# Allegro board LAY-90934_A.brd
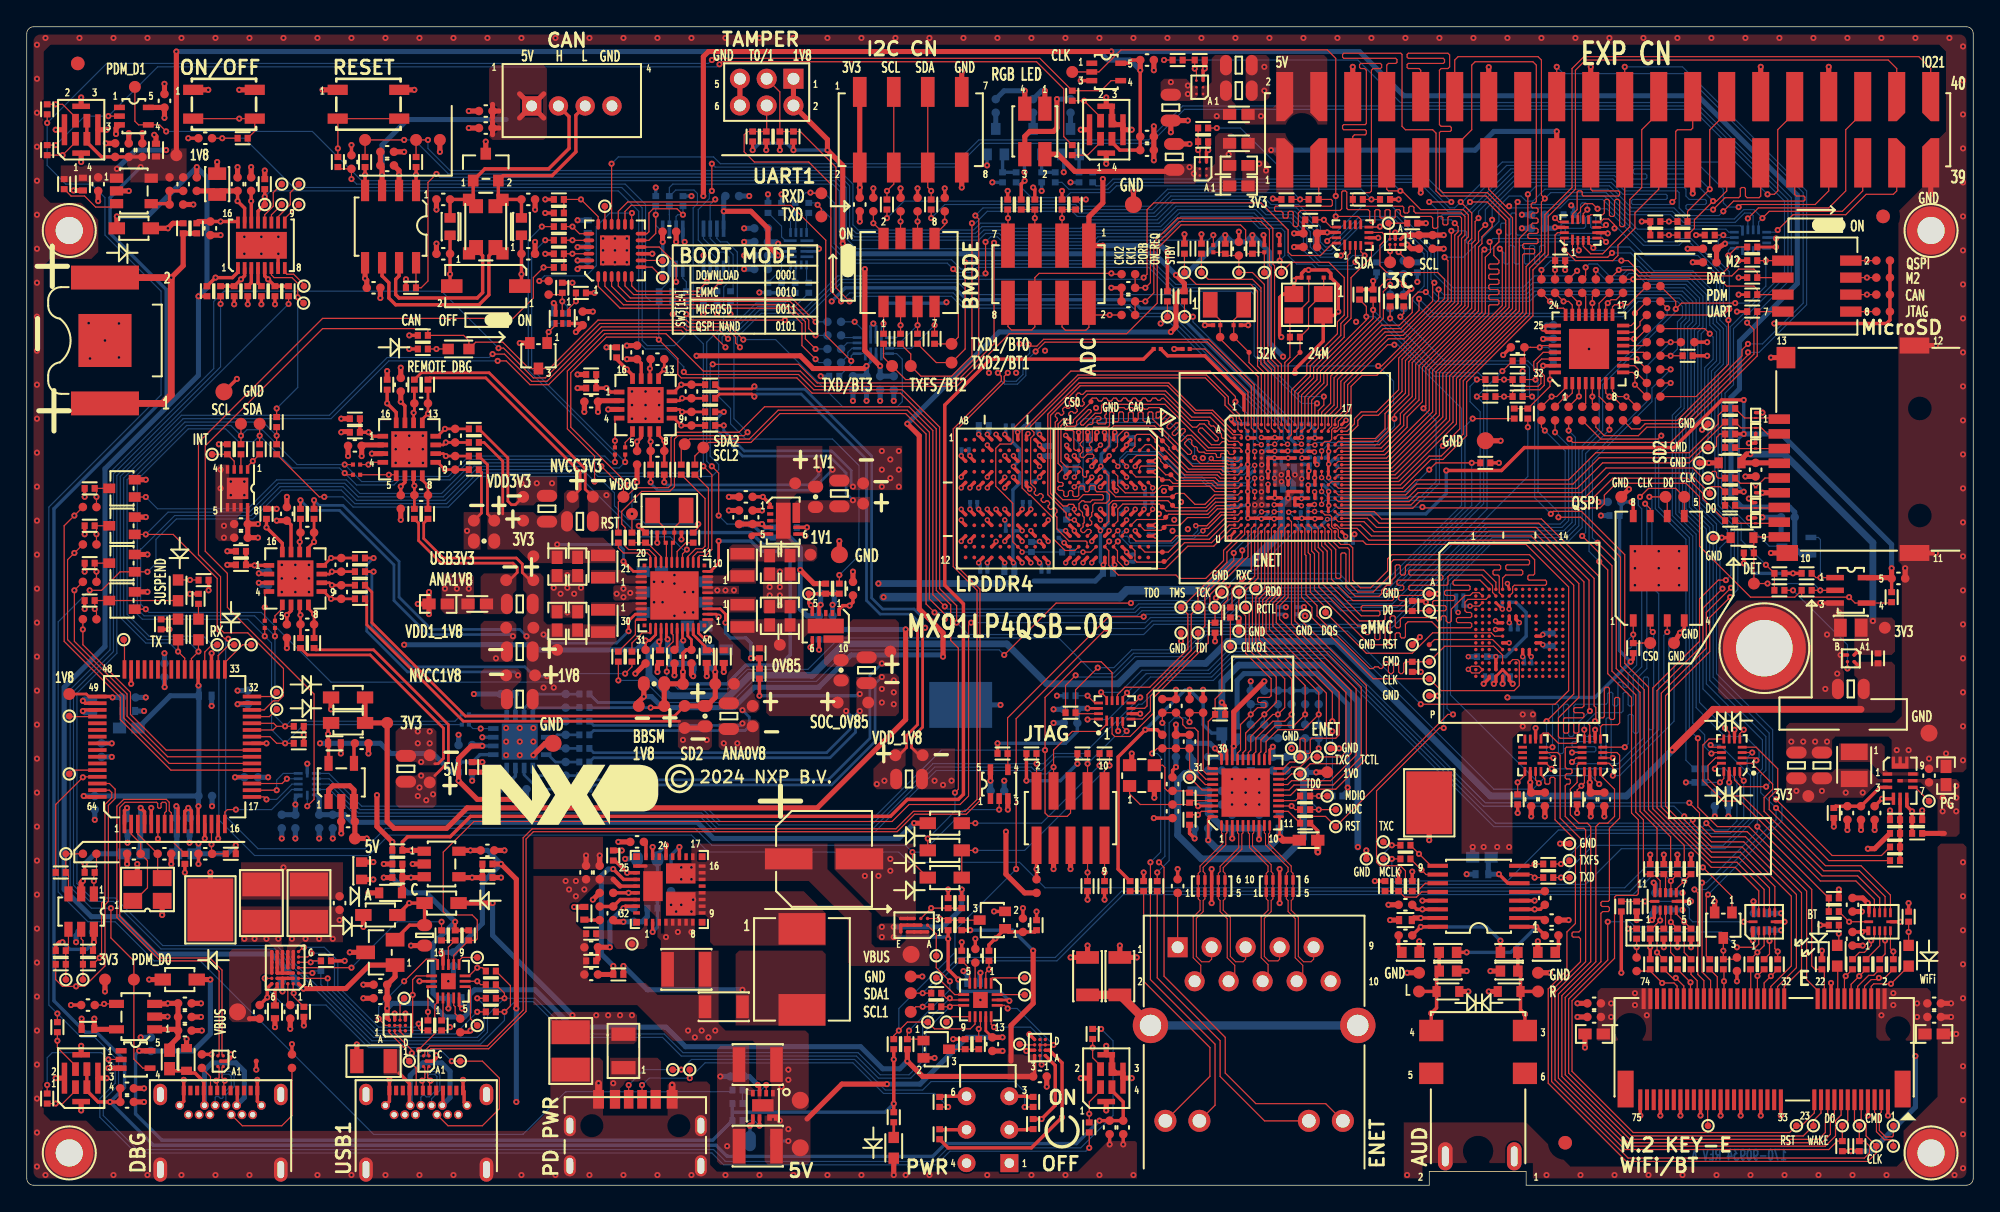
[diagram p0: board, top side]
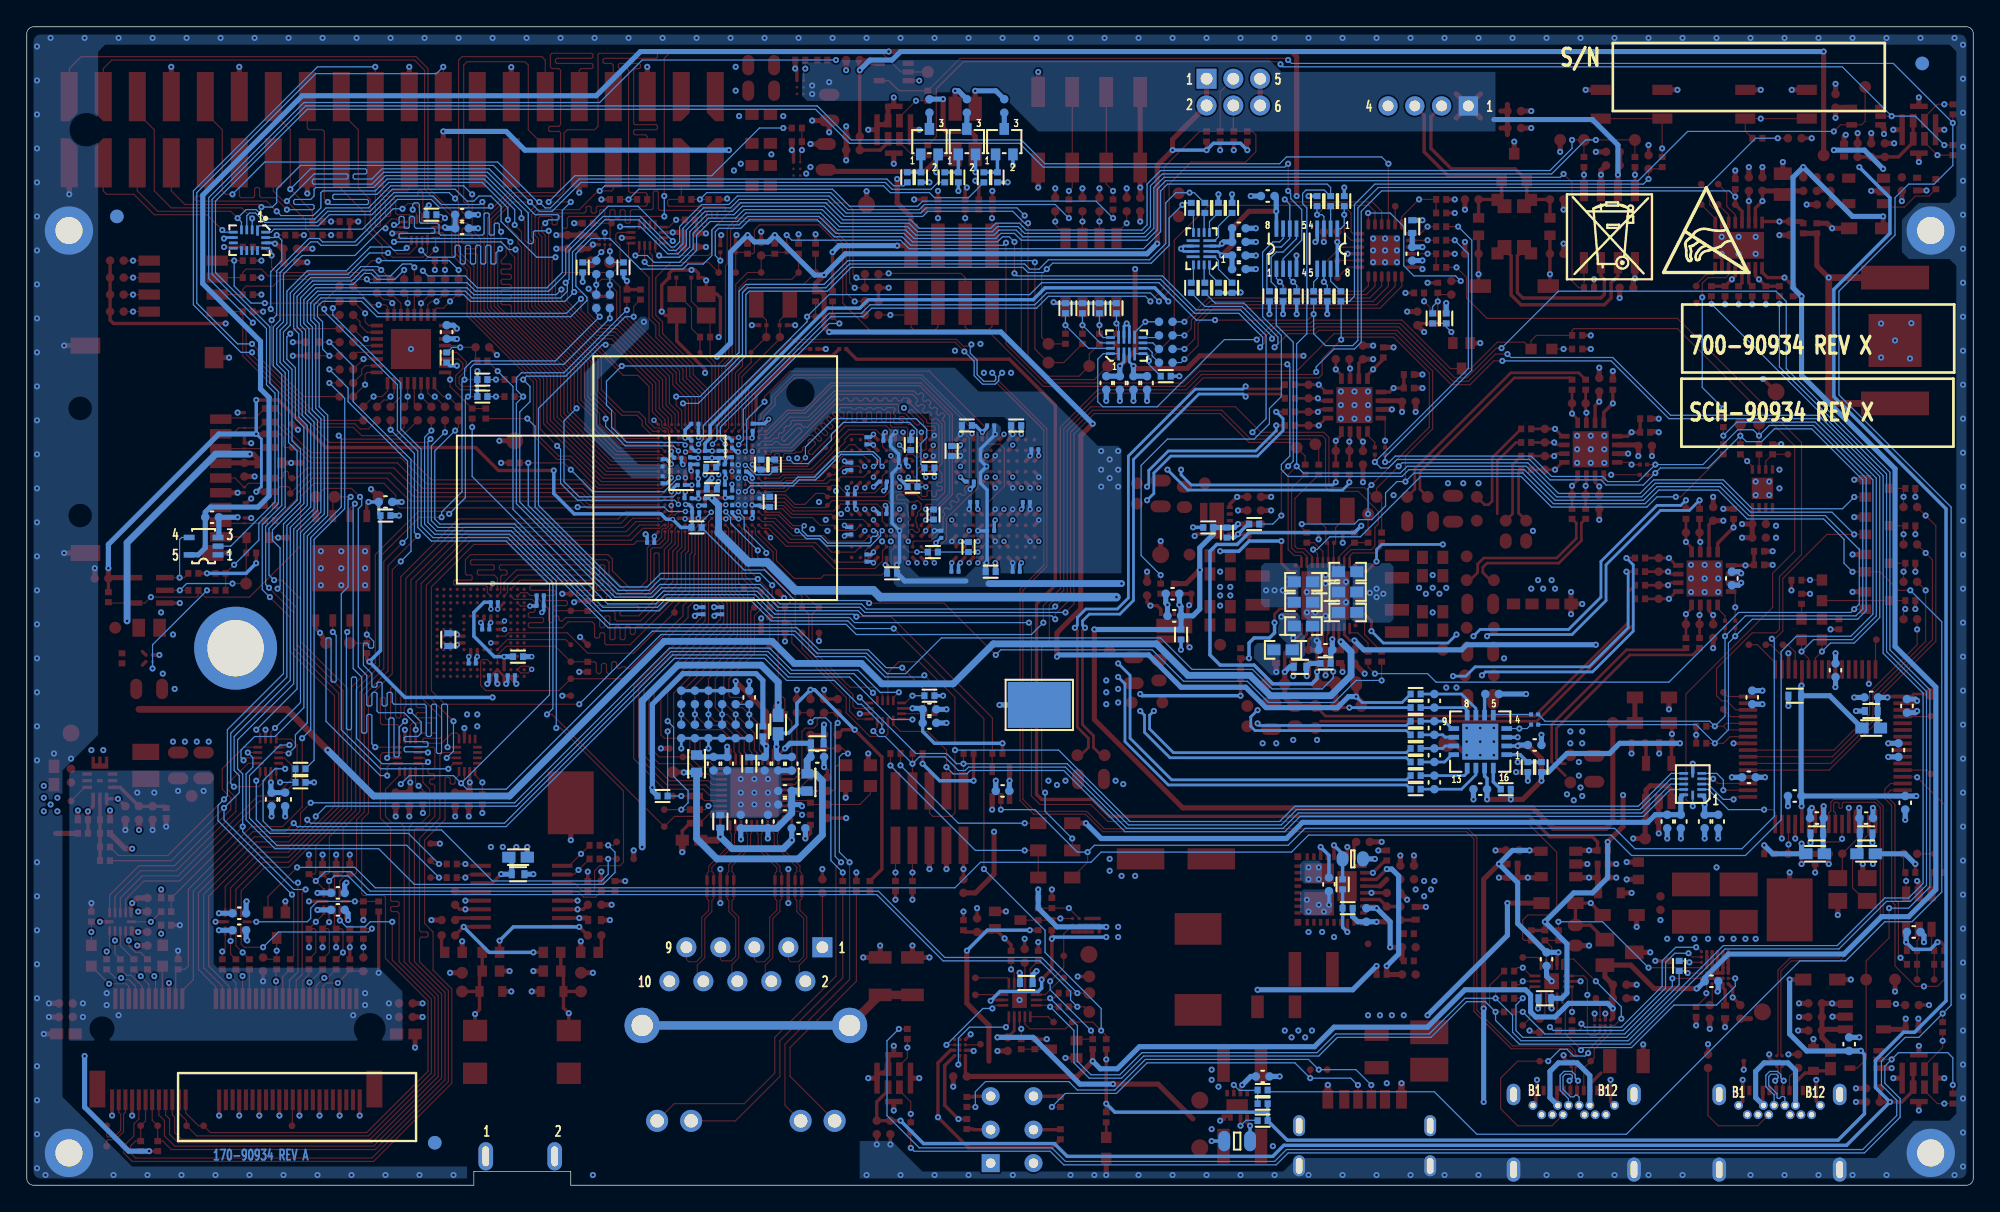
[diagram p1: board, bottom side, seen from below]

Outline 145.42 x 86.56 mm; copper layers: TOP, L2_GND, L3_PWR, BOTTOM. Coordinates in mm from the lower left corner of the outline.
Outline path: 0,86.05 arc(0.15,86.41) 0.51,86.56 144.91,86.56 arc(145.27,86.41) 145.42,86.05 145.42,0.51 arc(145.27,0.15) 144.91,0 112.01,0 112.01,1.02 104.77,1.02 104.77,0 0.51,0 arc(0.15,0.15) 0,0.51 0,86.05

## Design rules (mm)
constraint set DEFAULT: min track width 0.086
net group ETH1_TRX0: nets ETH1_TRX0_N ETH1_TRX0_P
net group ETH1_TRX1: nets ETH1_TRX1_N ETH1_TRX1_P
net group ETH1_TRX2: nets ETH1_TRX2_N ETH1_TRX2_P
net group ETH1_TRX3: nets ETH1_TRX3_N ETH1_TRX3_P
net group FT_USB: nets FT_USB_DN FT_USB_DP
net group M2_USB_D: nets M2_USB_DN M2_USB_DP
net group SD2_CLK: nets SD2_CLK SD_CLK
net group SD2_CMD: nets SD2_CMD SD_CMD
net group SD2_DATA0: nets SD2_DATA0 SD_DATA0
net group SD2_DATA1: nets SD2_DATA1 SD_DATA1
net group SD2_DATA2: nets SD2_DATA2 SD_DATA2
net group SD2_DATA3: nets SD2_DATA3 SD_DATA3
net group USB1: nets USB1_DN USB1_DP
net group USB_DBG: nets USB_DBG_DN USB_DBG_DP
net group USBC: nets USBC_DN USBC_DP
net group EXP_GPIO_IO08: nets EXP_GPIO_IO08 GPIO_IO08 SPI3_CS0
net group EXP_GPIO_IO09: nets EXP_GPIO_IO09 GPIO_IO09 SPI3_MISO
net group EXP_GPIO_IO10: nets EXP_GPIO_IO10 GPIO_IO10 SPI3_MOSI
net group EXP_GPIO_IO11: nets EXP_GPIO_IO11 GPIO_IO11 SPI3_CLK
net group GPIO_IO16: nets GPIO_IO16 GPIO_IO18 SAI3_TXBCLK/RXBCLK
net group GPIO_IO19: nets GPIO_IO19 SAI3_TX_SYNC SAI3_TXSYNC/RXSYNC
net group M2_SD_CLK: nets M2_SD_CLK QSPIA_SCLK SD3_CLK
net group M2_SD_DATA0: nets M2_SD_DATA0 QSPIA_DATA0 SD3_DATA0
net group M2_SD_DATA1: nets M2_SD_DATA1 QSPIA_DATA1 SD3_DATA1
net group M2_SD_DATA2: nets M2_SD_DATA2 QSPIA_DATA2 SD3_DATA2
net group M2_SD_DATA3: nets M2_SD_DATA3 QSPIA_DATA3 SD3_DATA3
net group M-DDR-ADDRESS: nets DRAM_CA0_A DRAM_CA1_A DRAM_CA2_A DRAM_CA3_A DRAM_CA4_A DRAM_CA5_A DRAM_CK_C_A DRAM_CK_T_A DRAM_CKE0_A DRAM_CKE1_A DRAM_NCS0_A DRAM_NCS1_A
net group M-DDR-DATA0: nets DRAM_DATA0_A DRAM_DATA1_A DRAM_DATA2_A DRAM_DATA3_A DRAM_DATA4_A DRAM_DATA5_A DRAM_DATA6_A DRAM_DATA7_A DRAM_DMI0_A DRAM_SDQS0_C_A DRAM_SDQS0_T_A
net group M-DDR-DATA1: nets DRAM_DATA8_A DRAM_DATA9_A DRAM_DATA10_A DRAM_DATA11_A DRAM_DATA12_A DRAM_DATA13_A DRAM_DATA14_A DRAM_DATA15_A DRAM_DMI1_A DRAM_SDQS1_C_A DRAM_SDQS1_T_A
net group M-GPIO: nets GPIO_IO00 GPIO_IO01 GPIO_IO02 GPIO_IO03 GPIO_IO04 GPIO_IO05 GPIO_IO06 GPIO_IO07 GPIO_IO12 GPIO_IO14 GPIO_IO15 GPIO_IO17 GPIO_IO20 GPIO_IO21
net group M-RX: nets ENET1_RD0 ENET1_RD1 ENET1_RD2 ENET1_RD3 ENET1_RX_CTL ENET1_RXC
net group M-TX: nets ENET1_TD0 ENET1_TD1 ENET1_TD2 ENET1_TD3 ENET1_TX_CTL ENET1_TXC
net group QSPIA_NSS0: nets M2_SD_CMD QSPIA_NSS0 SD3_CMD
net group SD1-EMMC: nets SD1_CLK SD1_CMD SD1_DATA0 SD1_DATA1 SD1_DATA2 SD1_DATA3 SD1_DATA4 SD1_DATA5 SD1_DATA6 SD1_DATA7 SD1_STROBE

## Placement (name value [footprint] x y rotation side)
BH1  $  [MH142P080]  3.17 71.34 0 top
BH2  $  [MH142P080]  142.26 71.34 90 top
BH3  $  [MH244-166T_202H]  129.81 40.13 0 top
BH4  $  [MH142P080]  3.17 2.41 0 top
BH5  $  [MH142P080]  142.26 2.41 0 top
BT1  $  [BATT_6P8MM_SM]  5.84 63.12 90 top
C1  $  [CC0402_25]  83.69 84.07 0 top
C2  $  [CC0805_OV]  90.55 83.69 0 top
C3  $  [CC0805_OV]  90.55 81.79 0 top
C4  $  [CC0402_25]  10.29 81.03 90 top
C5  $  [CC0805_OV]  85.47 80.52 270 top
C6  $  [CC0402_25]  34.29 80.26 180 top
C7  $  [CC0402_25]  34.29 78.99 180 top
C8  $  [CC0402_25]  83.69 78.36 0 top
C9  $  [CC0402_25]  13.34 78.23 180 top
C10  $  [CC0402_25]  6.6 77.34 90 top
C11  $  [CC0402_25]  7.62 77.34 90 top
C12  $  [CC0402_25]  8.64 77.34 90 top
C13  $  [CC0402_TOL0P15]  9.65 77.34 90 top
C14  $  [CC0402_25]  83.69 77.34 0 top
C15  $  [CC0402_25]  26.92 77.22 0 top
C16  $  [CC0805_OV]  85.72 76.84 90 top
C17  $  [CC0402_25]  24.26 76.45 90 top
C18  $  [CC0402_25]  26.92 76.2 0 top
C19  $  [CC0603]  90.55 76.2 0 top
C20  $  [CC0402_TOL0P15]  4.19 74.8 270 top
C21  $  [CC0402_25]  5.33 74.8 270 top
C22  56pF  [CC0402_25]  11.68 74.8 270 top
C23  $  [0805_CC]  14.22 74.8 90 top
C24  $  [CC0402_25]  15.75 74.8 90 top
C25  $  [CC0402_25]  16.76 74.8 90 top
C26  $  [CC0603]  90.55 74.68 0 top
C27  $  [CC0402_25]  31.12 73.66 0 top
C28  $  [CC0402_25]  37.46 73.66 0 top
C29  $  [CC0402_25]  62.23 73.28 270 top
C30  $  [CC0402_25]  13.72 71.5 270 top
C31  $  [CC0402_25]  48.01 71.25 0 top
C32  $  [CC0402_25]  95.88 71.12 180 top
C33  $  [CC0402_25]  104.01 70.49 270 top
C34  $  [CC0402_25]  105.03 70.49 270 top
C35  $  [CC0402_25]  95.88 70.1 180 top
C36  0.1uF  [CC0402_25]  90.55 69.98 90 top
C37  $  [CC0402_25]  125.73 69.98 180 top
C38  $  [CC0402_25]  31.12 69.6 180 top
C39  $  [CC0402_25]  37.46 69.6 0 top
C40  $  [CC0402_25]  125.73 68.96 180 top
C41  $  [0201_CC]  95.5 67.82 180 top
C42  $  [0201_CC]  97.16 67.82 0 top
C43  $  [CC0402_25]  25.91 67.06 0 top
C44  $  [CC0402_25]  82.3 67.06 180 top
C45  $  [CC0402_25]  82.3 66.04 180 top
C46  $  [CC0402_25]  41.53 64.77 90 top
C47  $  [0201_CC]  88.9 64.26 180 top
C48  $  [0201_CC]  90.42 64.26 0 top
C49  0.1uF  [CC0402_25]  111.38 62.61 180 top
C50  $  [CC0402_25]  45.59 62.23 90 top
C51  0.01uF  [CC0402_25]  47.12 61.72 180 top
C52  $  [CC0402_25]  27.94 59.82 90 top
C53  0.01uF  [CC0402_25]  49.66 59.31 90 top
C54  $  [CC0402_25]  42.16 58.55 180 top
C55  0.01uF  [CC0402_25]  29.46 58.42 180 top
C56  0.01uF  [CC0402_25]  49.66 57.28 270 top
C57  0.01uF  [CC0402_25]  32 56.01 90 top
C58  $  [CC0402_25]  24.51 55.25 180 top
C59  0.01uF  [CC0402_25]  47.12 54.86 180 top
C60  0.01uF  [CC0402_25]  32 53.98 270 top
C61  $  [CC0402_25]  129.16 53.47 270 top
C62  0.01uF  [CC0402_25]  29.46 51.56 180 top
C63  220PF  [CC0402_25]  53.72 51.44 180 top
C64  $  [CC0402_25]  19.43 50.17 90 top
C65  $  [CC0402_25]  53.21 49.91 90 top
C66  $  [CC0402_25]  54.23 49.91 90 top
C67  $  [CC0402_25]  16 49.4 180 top
C68  0.01uF  [CC0402_25]  20.96 48.77 180 top
C69  $  [0201_CC]  47.37 48.77 180 top
C70  $  [0201_CC]  48.64 48.77 0 top
C71  $  [CC0402_25]  16 48.39 180 top
C72  0.01uF  [CC0402_25]  23.5 46.36 90 top
C73  $  [CC0603]  55.5 46.36 270 top
C74  22uF  [CC0603]  57.02 46.36 270 top
C75  $  [CC0603]  39.62 46.23 270 top
C76  $  [CC0603]  41.15 46.23 270 top
C77  $  [CC0402_25]  139.83 45.34 0 top
C78  220PF  [CC0402_25]  61.72 44.58 90 top
C79  0.01uF  [CC0402_25]  23.5 44.32 270 top
C80  22uF  [CC0603]  30.73 43.43 180 top
C81  $  [CC0603]  55.5 42.55 90 top
C82  22uF  [CC0603]  57.02 42.55 90 top
C83  22uF  [CC0603]  39.62 42.16 90 top
C84  $  [CC0603]  41.15 42.16 90 top
C85  0.01uF  [CC0402_25]  20.96 41.91 180 top
C86  $  [0805_CC]  136.27 41.66 180 top
C87  $  [CC0402_25]  46.23 39.5 90 top
C88  $  [CC0402_TOL0P15]  47.31 39.5 270 top
C89  $  [CC0402_25]  48.39 39.5 270 top
C90  $  [CC0402_25]  49.66 39.5 270 top
C91  $  [CC0402_TOL0P15]  50.8 39.5 270 top
C92  $  [CC0402_TOL0P15]  52.07 39.5 270 top
C93  $  [CC0805_OV]  136.27 37.08 180 top
C94  470PF  [CC0402_25]  85.85 35.81 90 top
C95  470PF  [CC0402_25]  86.87 33.15 90 top
C96  $  [CC0402_TOL0P15]  22.99 33.02 0 top
C97  $  [CC0402_25]  25.02 33.02 0 top
C98  $  [CC0805_OV]  132.21 31.37 90 top
C99  $  [CC0805_OV]  134.11 31.37 90 top
C100  $  [CC0402_25]  142.11 30.61 90 top
C101  1uF  [0201_CC]  95.76 55.37 90 bottom
C102  $  [0201_CC]  95.5 56.9 0 bottom
C103  $  [CC0603]  143.38 30.61 90 top
C104  10uF  [0402_CC_NSP]  94.28 53.66 180 bottom
C105  1uF  [0201_CC]  94.87 42.93 270 bottom
C106  1uF  [0201_CC]  95.25 52.03 270 bottom
C107  1uF  [0201_CC]  95.3 53.59 90 bottom
C108  10uF  [0402_CC_NSP]  94.23 52.01 0 bottom
C109  1uF  [0201_CC]  93.47 42.93 270 bottom
C110  1uF  [0201_CC]  93.26 52.08 270 bottom
C111  1uF  [0201_CC]  93.29 53.59 90 bottom
C112  16pF  [CC0402_25]  85.6 29.97 90 top
C113  $  [CC0402_25]  112.39 28.83 270 top
C114  $  [CC0402_25]  113.41 28.83 270 top
C115  1uF  [0201_CC]  92.71 51.65 270 bottom
C116  1uF  [0201_CC]  94.74 51.05 270 bottom
C117  $  [CC0402_25]  116.84 28.83 270 top
C118  1uF  [0201_CC]  97.92 52.71 270 bottom
C119  1uF  [0201_CC]  97.92 53.98 90 bottom
C120  $  [CC0402_25]  117.86 28.83 270 top
C121  16pF  [CC0402_25]  85.6 27.94 270 top
C122  $  [CC0402_25]  136.02 27.81 90 top
C123  1000pF  [CC0402_25]  138.05 27.81 270 top
C124  $  [CC0402_25]  24 27.18 180 top
C125  $  [CC0402_25]  45.59 25.65 0 top
C127  $  [CC0402_25]  34.42 25.02 0 top
C128  27 PF  [CC0402_25]  8 24.77 180 top
C129  1uF  [0201_CC]  95.44 50.29 180 bottom
C130  1uF  [0201_CC]  96.77 54.36 0 bottom
C131  1uF  [0201_CC]  96.01 51.33 180 bottom
C132  1uF  [0201_CC]  98.81 48.01 180 bottom
C133  1uF  [0201_CC]  91.19 56.64 90 bottom
C134  27 PF  [CC0402_25]  10.29 24.77 0 top
C135  $  [CC0402_25]  13.34 24.77 180 top
C136  10uF  [0402_CC_NSP]  89.92 51.05 270 bottom
C137  1uF  [0201_CC]  92.71 50.55 270 bottom
C138  1uF  [0201_CC]  91.95 53.33 180 bottom
C139  1uF  [0201_CC]  91.44 50.29 180 bottom
C140  1uF  [0201_CC]  90.68 51.05 270 bottom
C141  $  [CASE_D_AL]  59.56 24.38 0 top
C142  $  [CC0402_25]  41.78 23.37 90 top
C143  $  [CC0402_25]  42.8 23.37 90 top
C144  1uF  [0201_CC]  93.73 54.61 270 bottom
C145  1uF  [0201_CC]  95.86 54.13 270 bottom
C146  1uF  [0201_CC]  96.52 52.32 0 bottom
C148  $  [CC0402_25]  85.98 22.35 90 top
C149  $  [CC0402_25]  113.41 21.46 270 top
C150  $  [CC1210]  17.53 21.08 90 top
C151  10uF  [0402_CC_NSP]  90.55 53.85 270 bottom
C152  $  [0201_CC]  92.73 54.13 90 bottom
C153  $  [0201_CC]  92.73 55.37 90 bottom
C154  $  [CC1210]  21.08 21.08 90 top
C155  1uF  [0201_CC]  94.74 54.61 270 bottom
C156  $  [CC0402_25]  23.37 21.08 90 top
C157  $  [CC0402_25]  103 20.96 0 top
C158  $  [CC0402_25]  136.4 20.96 270 top
C159  $  [CC0402_TOL0P15]  41.66 20.32 90 top
C160  $  [CC0402_25]  43.81 20.32 270 top
C161  $  [CC0402_TOL0P15]  103 19.81 180 top
C162  $  [CC0402_25]  113.92 19.81 0 top
C163  $  [CC0402_25]  74.42 19.43 90 top
C164  $  [CC0603_OV]  29.72 18.67 270 top
C165  $  [CC0402_25]  103 18.67 180 top
C166  $  [CC0402_25]  113.92 18.67 0 top
C167  $  [CC0402_25]  136.4 18.42 270 top
C168  $  [CC0402_25]  42.16 17.78 0 top
C169  $  [CC0402_25]  70.87 17.15 270 top
C170  $  [1210_CC]  49.28 16.13 180 top
C171  $  [0603_CC]  106.17 16 0 top
C172  $  [0603_CC]  110.74 16 0 top
C173  0.22uF  [CC0402_25]  42.16 15.75 180 top
C174  $  [1206_CC]  81.66 15.62 270 top
C175  $  [CC0402_25]  26.42 14.99 180 top
C176  $  [CC0402_25]  26.42 13.97 180 top
C177  $  [CC0402_25]  11.81 13.59 0 top
C178  $  [CC0402_25]  117.09 13.59 180 top
C179  $  [CC0402_25]  142.49 13.59 0 top
C180  $  [CC0402_25]  4.57 13.46 180 top
C181  $  [CC0402_25]  17.4 12.95 270 top
C182  $  [CC0402_TOL0P15]  18.54 12.95 270 top
C183  $  [CC0402_25]  19.69 12.95 270 top
C184  $  [CC0402_25]  11.81 12.57 0 top
C185  $  [CC0402_25]  117.09 12.57 180 top
C186  $  [CC0402_25]  142.49 12.57 0 top
C187  $  [CC0402_25]  32.38 11.94 90 top
C188  $  [CC0402_TOL0P15]  4.57 11.68 180 top
C189  $  [CC0402_25]  11.81 11.56 0 top
C190  $  [CC0603]  117.09 11.3 180 top
C191  $  [CC0603]  142.49 11.3 0 top
C192  $  [CC0402_25]  72.14 10.54 90 top
C193  $  [CC1210]  40.64 10.03 270 top
C194  $  [1210_CC]  54.61 9.02 180 top
C195  $  [CC0402_25]  75.69 8.13 0 top
C196  $  [CC0402_25]  7.49 7.24 0 top
C197  $  [CC0402_25]  7.49 6.22 0 top
C198  $  [CC0402_25]  80.9 4.32 270 top
C199  $  [CC0402_25]  81.91 4.32 270 top
C200  $  [1210_CC]  54.61 2.92 180 top
C201  $  [0402_CC_NSP]  80.77 45.72 0 bottom
C202  $  [0402_CC_NSP]  73.41 45.85 180 bottom
C203  $  [0201_CC]  81.15 55.63 0 bottom
C204  $  [0201_CC]  73.41 56.77 0 bottom
C205  $  [0201_CC]  80.01 54.23 180 bottom
C206  $  [0402_CC_NSP]  76.33 54.86 90 bottom
C207  $  [0402_CC_NSP]  75.18 56.77 180 bottom
C208  $  [0201_CC]  83.82 48.9 270 bottom
C209  $  [0201_CC]  73.41 48.9 180 bottom
C210  $  [0201_CC]  74.93 52.58 0 bottom
C211  $  [0201_CC]  77.09 48.64 270 bottom
C212  $  [0201_CC]  76.07 45.85 180 bottom
C213  $  [0201_CC]  74.68 51.05 180 bottom
C214  $  [0201_CC]  83.82 53.72 90 bottom
C215  $  [0402_CC_NSP]  71.5 56.77 180 bottom
C216  $  [0201_CC]  82.68 46.86 90 bottom
C217  $  [0201_CC]  81.47 50.17 180 bottom
C218  $  [0201_CC]  82.68 55.63 270 bottom
C219  $  [0201_CC]  70.1 54.99 180 bottom
C220  $  [0201_CC]  70.74 51.05 0 bottom
C221  $  [0201_CC]  81.42 52.58 180 bottom
C222  $  [0201_CC]  71.5 45.85 180 bottom
C223  $  [CC0402_25]  52.7 73.91 0 bottom
C224  $  [CC0402_25]  112.9 72.52 180 bottom
C225  $  [CC0402_TOL0P15]  41.91 71.63 90 bottom
C226  $  [CC0402_25]  112.9 71.5 180 bottom
C227  $  [CC0402_25]  54.86 71.5 180 bottom
C228  $  [CC0402_25]  54.86 70.49 180 bottom
C229  $  [CC0402_25]  41.91 69.6 270 bottom
C230  $  [CC0402_25]  54.86 69.47 180 bottom
C231  $  [CC0402_25]  54.86 68.45 180 bottom
C232  $  [CC0402_25]  114.05 63.75 90 bottom
C233  $  [CC0402_25]  64.77 59.94 270 bottom
C234  $  [CC0402_25]  63.75 59.94 270 bottom
C235  $  [CC0402_25]  62.74 59.94 270 bottom
C236  $  [CC0402_25]  61.72 59.94 270 bottom
C237  $  [CC0402_25]  118.62 51.05 180 bottom
C238  $  [0402_CC_NSP]  118.62 50.04 180 bottom
C239  $  [CC0603]  46.74 45.85 180 bottom
C240  $  [CC0402_25]  18.03 45.34 270 bottom
C241  $  [CC0603]  50.04 45.09 0 bottom
C242  $  [CC0603]  46.74 44.32 180 bottom
C243  $  [CC0402_25]  59.82 44.2 0 bottom
C244  $  [0201_CC]  107.06 44.07 180 bottom
C245  $  [0201_CC]  110.49 43.56 180 bottom
C246  $  [CC0603]  50.04 43.56 0 bottom
C247  $  [0201_CC]  107.06 43.31 180 bottom
C248  $  [CC0603]  46.74 42.8 180 bottom
C249  $  [CC0402_25]  59.69 42.55 0 bottom
C250  $  [CC0603]  50.04 41.78 180 bottom
C251  $  [0201_CC]  111.12 41.53 0 bottom
C252  $  [CC0402_TOL0P15]  113.92 40.77 90 bottom
C253  $  [CC0603]  51.56 40.01 0 bottom
C254  $  [CC0402_25]  48.39 40.01 0 bottom
C255  $  [0402_CC_NSP]  108.71 39.5 180 bottom
C256  $  [0201_CC]  112.14 38.99 180 bottom
C257  $  [CC0402_TOL0P15]  50.29 38.74 180 bottom
C258  $  [CC0402_25]  10.29 38.48 90 bottom
C259  $  [0201_CC]  110.62 38.1 0 bottom
C260  $  [0201_CC]  109.22 38.1 0 bottom
C261  $  [CC0402_TOL0P15]  13.34 36.58 0 bottom
C262  16pF  [CC0402_25]  91.44 36.45 90 bottom
C263  $  [CC0402_25]  16.51 36.45 90 bottom
C264  $  [CC0402_25]  7.62 36.45 0 bottom
C265  0.01uF  [CC0402_25]  40.26 36.2 90 bottom
C266  $  [CC0402_25]  4.95 35.81 270 bottom
C267  $  [CC0402_25]  77.98 35.56 180 bottom
C268  $  [CC0402_TOL0P15]  7.62 35.43 0 bottom
C269  $  [CC0402_25]  77.98 34.54 180 bottom
C270  0.01uF  [CC0402_25]  40.26 34.16 90 bottom
C271  $  [CC0402_TOL0P15]  86.36 33.02 180 bottom
C272  $  [CC0402_25]  32.77 32.89 180 bottom
C273  $  [CC0402_25]  5.59 32.51 270 bottom
C274  0.01uF  [CC0402_25]  40.26 32.13 270 bottom
C275  $  [CC0402_25]  86.36 32 180 bottom
C276  $  [CC0402_25]  94.11 31.5 270 bottom
C277  $  [CC0402_25]  93.09 31.5 270 bottom
C278  $  [CC0402_TOL0P15]  91.44 31.5 270 bottom
C279  $  [CC0402_25]  90.3 31.5 270 bottom
C280  $  [CC0402_25]  89.28 31.5 270 bottom
C281  $  [CC0402_25]  88.27 31.5 270 bottom
C282  $  [CC0402_25]  16.76 30.48 0 bottom
C283  0.01uF  [CC0402_25]  40.26 30.1 270 bottom
C284  $  [CC0402_25]  36.83 29.59 0 bottom
C285  $  [CC0402_25]  88.77 29.46 0 bottom
C286  $  [CC0402_25]  72.52 29.46 0 bottom
C287  $  [CC0402_25]  13.34 29.08 0 bottom
C288  $  [CC0402_25]  127.13 28.83 270 bottom
C289  $  [CC0402_25]  126.11 28.83 270 bottom
C290  $  [CC0402_25]  5.08 28.58 270 bottom
C291  $  [CC0402_25]  88.77 28.45 0 bottom
C292  $  [CC0402_25]  11.68 27.43 0 bottom
C293  $  [CC0402_25]  8 27.43 180 bottom
C294  $  [CC0402_TOL0P15]  93.6 27.18 90 bottom
C295  $  [CC0402_25]  92.08 27.18 90 bottom
C296  $  [CC0402_25]  90.04 27.18 90 bottom
C297  $  [CC0402_25]  22.86 27.18 270 bottom
C298  $  [CC0402_25]  21.84 27.18 270 bottom
C299  $  [CC0402_25]  20.07 27.18 270 bottom
C300  $  [CC0402_25]  19.05 27.18 270 bottom
C301  $  [CC0402_25]  87.76 26.67 180 bottom
C302  $  [CC0402_TOL0P15]  11.68 26.29 0 bottom
C303  $  [CC0402_TOL0P15]  8 26.29 180 bottom
C304  $  [CC0603_OV]  46.35 24.38 180 bottom
C305  $  [CC0402_TOL0P15]  108.71 23.24 180 bottom
C306  $  [CC0402_25]  48.13 22.48 270 bottom
C307  $  [CC0402_25]  122.17 21.84 0 bottom
C308  $  [CC0402_25]  122.17 20.57 0 bottom
C309  $  [CC0402_25]  129.54 20.32 0 bottom
C310  $  [CC0402_25]  129.54 19.05 0 bottom
C311  $  [CC0402_25]  4.45 18.92 180 bottom
C312  $  [CC0402_25]  31.88 16.89 90 bottom
C313  $  [CC0402_25]  19.56 15.24 180 bottom
C314  $  [CC0402_TOL0P15]  70.74 15.11 180 bottom
C315  $  [CC0402_TOL0P15]  32 13.97 0 bottom
C316  $  [CC0402_25]  9.27 10.54 90 bottom
C317  $  [CC0402_25]  53.09 8.13 180 bottom
C318  $  [CC0402_25]  131.57 49.91 180 bottom
D1  $  [LED4_3P4X3_SM]  75.31 78.74 0 top
D2  $  [SOT23_A]  34.29 76.07 0 top
D3  $  [SOD323]  8 71.5 90 top
D5  $  [LED_0603]  32.26 62.48 0 top
D6  $  [DSN0603-2]  129.16 57.53 90 top
D7  $  [DSN0603-2]  129.16 56.39 270 top
D9  $  [DSN0603-2]  129.16 55.25 90 top
D10  $  [DIODE2_SOD523]  127.25 53.98 180 top
D11  $  [DSN0603-2]  129.16 51.94 270 top
D12  $  [DSN0603-2]  129.16 50.8 90 top
D13  $  [DSN0603-2]  129.16 49.66 90 top
D14  $  [DIODE2_SOD523]  128.14 48.39 180 top
D15  $  [LED_0603_11MIL]  11.3 44.45 270 top
D16  $  [LED_0603]  11.3 41.53 270 top
D17  $  [LED_0603_11MIL]  12.83 41.53 270 top
D18  $  [SOD323]  24 36.45 90 top
D19  $  [SOD323]  24 34.54 90 top
D20  $  [SOD323]  68.58 27.05 90 top
D22  $  [SOD323]  68.58 25.02 90 top
D23  BAT54HT1  [SOD323]  68.58 22.99 90 top
D24  $  [SOD323]  26.42 20.19 90 top
D25  $  [SOD323]  30.99 21.08 270 top
D26  $  [LED_0603_11MIL]  135.26 17.15 270 top
D27  $  [LED_0603]  140.59 17.15 270 top
D28  $  [LED_0603]  64.77 2.79 270 top
D29  BZX585-B3V3  [SOD523]  27.18 21.84 180 top
D30  BAT54HT1  [SOD323]  11.43 15.37 270 top
F1  $  [FUSE_3P4X1P8]  44.58 10.03 90 top
F2  $  [FUSE_3P4X1P8]  25.91 9.27 180 top
GND1  TP_35MIL  [TESTPOINT_35MIL]  30.86 78.11 0 top
GND2  TP_35MIL  [TESTPOINT_35MIL]  66.04 15.6 0 top
GND3  -  [TPAD_015]  79.88 58.08 0 top
GND4  -  [TPAD_020]  125.6 56.9 0 top
GND5  -  [TPAD_015]  87.86 54.33 0 top
GND6  -  [TPAD_020]  124.97 53.98 0 top
GND7  TP_35MIL  [TESTPOINT_35MIL]  119.13 51.44 0 top
GND8  -  [TPAD_015]  86.23 51.05 0 top
GND9  -  [TPAD_015]  86.74 49.02 0 top
GND10  -  [TPAD_015]  85.6 48.9 0 top
GND11  -  [TPAD_020]  125.98 48.39 0 top
GND12  -  [TPAD_020]  89.28 44.32 0 top
GND13  -  [TPAD_020]  104.77 44.2 0 top
GND14  $  [TEST_PIN_TP107]  69.77 35.89 180 bottom
GND15  -  [TPAD_020]  103.5 40.39 0 top
GND16  -  [TPAD_020]  90.55 41.4 0 top
GND17  TP_35MIL  [TESTPOINT_35MIL]  123.06 40.51 0 top
GND18  -  [TPAD_020]  95.5 42.55 0 top
GND19  -  [TPAD_020]  104.77 36.58 0 top
GND20  -  [TPAD_020]  97.41 32.64 0 top
GND21  -  [TPAD_020]  94.49 32.64 0 top
GND22  $  [TEST_PIN_TP107]  104.77 28.58 90 top
GND23  -  [TPAD_020]  115.25 25.53 0 top
GND24  -  [TPAD_020]  100.08 24.38 0 top
GND25  $  [TEST_PIN_TP107]  13.72 20.57 90 top
GND26  TP_35MIL  [TESTPOINT_35MIL]  104.01 15.88 0 top
GND27  TP_35MIL  [TESTPOINT_35MIL]  112.9 15.88 0 top
GND28  -  [TPAD_015]  17.14 9.27 0 top
J1  $  [HDR203_TMM_210H]  57.28 82.68 180 top
J2  $  [CON1X4_2MM_TH_303H]  37.72 80.65 180 top
J3  $  [CON_2X4_SKT_100_SM]  66.04 78.87 90 top
J4  $  [HDR220_TSM_A_SM]  118.11 78.87 90 top
J5  $  [HDR204_TMM_SM]  76.33 68.07 270 top
J6  $  [CON9_SDCARD_1P1MM]  138.18 54.99 90 top
J7  $  [HDR205_10M_50_SM_K]  77.98 27.43 0 top
J8  $  [CON67_0P5_TYPE-E_22X7P3_RA_270H]  129.79 10.16 180 top
J9  $  [CON_RJ45_10_2LED_TH]  85.98 17.78 180 top
J10  $  [CON6_AUDIOJACK_RA_TH]  111.12 2.16 90 top
J11  $  [CON24_USB_TYPEC_RA_SMT_TH_2P2L]  17.53 5.97 0 top
J12  $  [CON24_USB_TYPEC_RA_SMT_TH_2P2L]  32.89 5.97 0 top
J13  $  [USB6P_TYPEC_RA_SM]  45.47 3.18 0 top
L1  $  [IND_0603]  90.55 80.01 180 top
L2  $  [IND_0603]  90.55 77.85 0 top
L3  DLW43SH510XK2  [IND_DLW43]  34.29 71.63 90 top
L4  $  [IND4_AMCW3225_SMT]  34.29 71.63 90 top
L5  $  [IND_2016A]  53.47 46.36 90 top
L6  $  [IND_2016A]  43.05 46.23 90 top
L7  $  [IND_0603]  33.66 43.43 180 top
L8  $  [IND_2016A]  53.47 42.55 270 top
L9  $  [IND_2016A]  43.05 42.16 270 top
L10  $  [IND_SPH2520]  136.53 31.37 270 top
L11  $  [IND_0603]  95.76 25.78 180 top
L12  $  [IND2_7P3X6P8_SM]  57.91 16.13 270 top
L13  $  [IND_0603]  10.67 9.4 90 top
L14  $  [IND_0603]  89.28 34.42 270 bottom
L15  $  [IND_0603]  7.62 34.16 180 bottom
L16  $  [IND_0603]  11.81 24.77 180 bottom
L17  $  [IND_0603]  8 24.77 0 bottom
L18  $  [IND_0603]  108.71 24.51 180 bottom
NOREF  -  []  57.91 13.1 90 top
NOREF#2  -  []  37.99 0.3 90 top
NOREF#3  -  []  21.63 29.17 90 top
NOREF#4  -  []  17.03 69.03 0 top
NOREF#5  -  []  42.73 71.05 90 top
NOREF#6  -  []  82.06 76.82 90 top
NOREF#7  -  []  133.54 6.39 0 top
NOREF#8  -  []  48.26 24.55 0 top
NOREF#9  -  []  41.58 71.05 0 top
NOREF#10  -  []  46.98 38.92 90 top
NOREF#11  -  []  21.63 29.17 90 top
NOREF#12  -  []  0 95.45 0 top
NOREF#13  -  []  129.79 10.16 0 top
NOREF#14  -  []  7.43 25.96 90 top
NOREF#15  -  []  57.03 70.18 90 top
NOREF#16  -  []  41.66 19.85 90 top
NOREF#17  -  []  3.17 2.41 0 top
NOREF#18  -  []  7.53 26.29 0 top
NOREF#19  -  []  140.14 7.19 90 top
NOREF#20  -  []  32.3 13.99 90 top
NOREF#21  -  []  18.03 17.73 0 top
NOREF#22  -  []  70.45 12.59 0 top
NOREF#23  -  []  11.11 26.61 0 top
NOREF#24  -  []  58.14 40.73 90 top
NOREF#25  -  []  34.76 31.07 90 top
NOREF#26  -  []  120.79 13.94 0 top
NOREF#27  -  []  80.22 7.33 0 top
NOREF#28  -  []  48.72 4.45 90 top
NOREF#29  -  []  87.38 82.54 0 top
NOREF#30  -  []  48.01 22.1 0 top
NOREF#31  -  []  3.64 78.19 0 top
NOREF#32  -  []  30.15 16.59 0 top
NOREF#33  -  []  34.04 26.92 0 top
NOREF#34  -  []  76.06 77.04 90 top
NOREF#35  -  []  119.79 11.69 0 top
NOREF#36  -  []  9.98 1.17 0 top
NOREF#37  -  []  48.01 22.1 90 top
NOREF#38  -  []  48.2 58.62 90 top
NOREF#39  -  []  53.97 4.94 90 top
NOREF#40  -  []  60.19 42.76 0 top
NOREF#41  -  []  48.86 21.02 90 top
NOREF#42  -  []  118.87 50.15 0 top
NOREF#43  -  []  50.36 1.45 90 top
NOREF#44  -  []  128.74 20.59 0 top
NOREF#45  -  []  137.38 20.59 0 top
NOREF#46  -  []  45.25 56.32 0 top
NOREF#47  -  []  28.54 11.29 90 top
NOREF#48  -  []  45.9 45.47 90 top
NOREF#49  -  []  19.58 -2.63 90 top
NOREF#50  -  []  90.23 48.83 0 top
NOREF#51  -  []  108.42 9.56 0 top
NOREF#52  -  []  142.13 47.59 90 top
NOREF#53  -  []  55.54 48.66 0 top
NOREF#54  -  []  137.63 20.36 0 top
NOREF#55  -  []  44.15 56.22 90 top
NOREF#56  -  []  45.9 45.87 0 top
NOREF#57  -  []  139 29.73 0 top
NOREF#58  -  []  50.47 38.92 90 top
NOREF#59  -  []  144.91 0 90 top
NOREF#60  -  []  104.93 11.56 0 top
NOREF#61  -  []  129.16 56.19 90 top
NOREF#62  -  []  134.09 3.3 0 top
NOREF#63  -  []  7.43 25.96 0 top
NOREF#64  -  []  47.31 39.02 90 top
NOREF#65  -  []  26.84 12.59 0 top
NOREF#66  -  []  54.24 5.06 90 top
NOREF#67  -  []  7.15 35.43 0 top
NOREF#68  -  []  87.38 81.54 90 top
NOREF#69  -  []  120.54 6.39 0 top
NOREF#70  -  []  75.04 11.14 0 top
NOREF#71  -  []  7.25 11.02 90 top
NOREF#72  -  []  69.66 56.36 0 top
NOREF#73  -  []  69.91 -0.5 90 top
NOREF#74  -  []  117.96 65.03 0 top
NOREF#75  -  []  25.34 1.17 0 top
NOREF#76  -  []  56.71 71.33 0 top
NOREF#77  -  []  87.44 75.25 90 top
NOREF#78  -  []  50.57 -1.65 90 top
NOREF#79  -  []  49.79 46.54 0 top
NOREF#80  -  []  104.93 11.56 0 top
NOREF#81  -  []  9.98 76.77 90 top
NOREF#82  -  []  130.93 48.44 90 top
NOREF#83  -  []  45.9 45.87 0 top
NOREF#84  -  []  29.85 8.66 90 top
NOREF#85  -  []  135.78 38.88 0 top
NOREF#86  -  []  108.14 22.92 90 top
NOREF#87  -  []  9.98 1.17 90 top
NOREF#88  -  []  0.75 86.56 0 top
NOREF#89  -  []  93.27 25.45 90 top
NOREF#90  -  []  35.85 31.17 90 top
NOREF#91  -  []  130.84 18.79 90 top
NOREF#92  -  []  18.28 71.93 0 top
NOREF#93  -  []  139.95 28.88 0 top
NOREF#94  -  []  137.3 211.27 90 top
NOREF#95  -  []  17.53 70.23 90 top
NOREF#96  -  []  54.24 6.88 0 top
NOREF#97  -  []  92.62 25.45 0 top
NOREF#98  -  []  9.65 76.87 90 top
NOREF#99  -  []  87.44 76.64 0 top
NOREF#100  -  []  70.14 46.91 0 top
NOREF#101  -  []  91.77 32.07 0 top
NOREF#102  -  []  129.16 51.74 90 top
NOREF#103  -  []  48.77 30.35 0 top
NOREF#104  -  [unnamed#2]  114.94 3.18 0 top
NOREF#105  -  []  45.56 23.85 0 top
NOREF#106  -  []  40.37 -1.65 0 top
NOREF#107  -  []  137.63 20.36 0 top
NOREF#108  -  []  6.3 12.01 90 top
NOREF#109  -  []  10.75 5.27 0 top
NOREF#110  -  []  19.9 17.46 0 top
NOREF#111  -  []  91.44 31.02 90 top
NOREF#112  -  []  12.08 5.27 0 top
NOREF#113  -  []  57.03 69.38 0 top
NOREF#114  -  []  65 18.65 90 top
NOREF#115  -  []  135.78 38.88 90 top
NOREF#116  -  []  22.63 0.3 90 top
NOREF#117  -  []  63.85 62.11 90 top
NOREF#118  -  []  3.64 7.33 0 top
NOREF#119  -  []  16.73 7.08 0 top
NOREF#120  -  []  16.08 5.27 0 top
NOREF#121  -  [unnamed#3]  93.98 52.83 0 top
NOREF#122  -  []  35.73 83.6 0 top
NOREF#123  -  []  130.88 47.59 90 top
NOREF#124  -  []  19.09 43.36 0 top
NOREF#125  -  []  61.9 61.79 0 top
NOREF#126  -  []  30.55 55.32 90 top
NOREF#127  -  []  129.32 57.22 90 top
NOREF#128  -  []  57.06 68.77 90 top
NOREF#129  -  []  70.14 46.91 90 top
NOREF#130  -  []  93.6 26.7 90 top
NOREF#131  -  []  32.85 13.89 90 top
NOREF#132  -  []  18.22 13.53 0 top
NOREF#133  -  []  45.9 42.27 90 top
NOREF#134  -  []  25.34 1.17 90 top
NOREF#135  -  []  26.12 5.27 0 top
NOREF#136  -  []  62.65 62.11 0 top
NOREF#137  -  []  57.06 68.77 0 top
NOREF#138  -  []  15 50.66 90 top
NOREF#139  -  []  87.18 81.35 90 top
NOREF#140  -  []  141.03 47.24 0 top
NOREF#141  -  []  41.91 71.15 90 top
NOREF#142  -  []  101.83 70.29 0 top
NOREF#143  -  []  26.25 52.54 0 top
NOREF#144  -  []  79.4 78.87 0 top
NOREF#145  -  []  101.64 70.07 90 top
NOREF#146  -  []  18.3 17.06 90 top
NOREF#147  -  []  31.9 16.49 0 top
NOREF#148  -  []  50.89 46.57 0 top
NOREF#149  -  []  30.7 16.49 0 top
NOREF#150  -  []  3.87 74.23 90 top
NOREF#151  -  []  108.24 23.24 0 top
NOREF#152  -  []  17.99 43.26 0 top
NOREF#153  -  []  106.21 19.04 0 top
NOREF#154  -  []  129.16 50.6 90 top
NOREF#155  -  []  129 49.97 0 top
NOREF#156  -  []  128.99 20.36 0 top
NOREF#157  -  []  105.07 -0.09 90 top
NOREF#158  -  []  26.25 52.54 90 top
NOREF#159  -  []  129 55.56 0 top
NOREF#160  -  []  27.44 5.27 0 top
NOREF#161  -  []  32.58 14.3 90 top
NOREF#162  -  []  106.02 -2.19 90 top
NOREF#163  -  []  46.78 22.35 0 top
NOREF#164  -  []  45.47 24.63 0 top
NOREF#165  -  []  46.59 46.54 0 top
NOREF#166  -  []  4.06 6.25 90 top
NOREF#167  -  []  26.12 5.27 90 top
NOREF#168  -  []  3.87 74.23 0 top
NOREF#169  -  []  131.43 61.84 0 top
NOREF#170  -  []  49.82 38.74 0 top
NOREF#171  -  []  87.18 82.74 0 top
NOREF#172  -  []  131.53 47.24 0 top
NOREF#173  -  []  5.15 12.01 0 top
NOREF#174  -  []  54.51 12.48 90 top
NOREF#175  -  []  130.93 48.44 90 top
NOREF#176  -  []  105.41 19.31 90 top
NOREF#177  -  []  81.07 78.19 90 top
NOREF#178  -  []  101.83 70.29 0 top
NOREF#179  -  []  129.16 49.46 90 top
NOREF#180  -  []  50.89 46.57 0 top
NOREF#181  -  []  80.22 78.19 0 top
NOREF#182  -  []  139.23 19.01 90 top
NOREF#183  -  []  105.07 12.76 0 top
NOREF#184  -  []  34.94 -2.63 90 top
NOREF#185  -  []  12.26 25.96 90 top
NOREF#186  -  []  51.74 38.92 0 top
NOREF#187  -  []  119.44 7.19 0 top
NOREF#188  -  []  49.72 38.41 90 top
NOREF#189  -  []  58.69 40.81 90 top
NOREF#190  -  []  19.28 68.53 90 top
NOREF#191  -  []  106.21 19.04 0 top
NOREF#192  -  []  129.16 55.05 90 top
NOREF#193  -  []  70.21 1.65 90 top
NOREF#194  -  []  46.59 41.59 90 top
NOREF#195  -  []  2.81 8 0 top
NOREF#196  -  []  14.49 8.66 90 top
NOREF#197  -  []  49.79 46.54 0 top
NOREF#198  -  []  72.46 14.79 90 top
NOREF#199  -  []  26.12 5.27 90 top
NOREF#200  -  []  102.52 19.81 0 top
NOREF#201  -  []  120.54 6.39 0 top
NOREF#202  -  []  69.9 12.49 90 top
NOREF#203  -  []  52.07 39.02 90 top
NOREF#204  -  []  18.25 31.02 0 top
NOREF#205  -  []  4.49 78.19 90 top
NOREF#206  -  []  129 56.08 0 top
NOREF#207  -  []  29.44 9.88 0 top
NOREF#208  -  []  101.83 70.29 90 top
NOREF#209  -  []  14.48 9.27 90 top
NOREF#210  -  []  80.64 77.12 90 top
NOREF#211  -  [unnamed#2]  3.81 83.82 0 top
NOREF#212  -  []  81.07 7.33 90 top
NOREF#213  -  []  118.79 6.81 0 top
NOREF#214  -  []  0.25 60.58 90 top
NOREF#215  -  []  22.51 33.02 0 top
NOREF#216  -  []  45.9 45.47 90 top
NOREF#217  -  []  70.45 12.59 90 top
NOREF#218  -  []  64.46 62.14 90 top
NOREF#219  -  []  27.09 7.08 0 top
NOREF#220  -  []  4.49 7.33 90 top
NOREF#221  -  []  129.16 57.33 90 top
NOREF#222  -  []  131.53 47.24 90 top
NOREF#223  -  []  4.1 11.68 0 top
NOREF#224  -  []  90.23 48.83 0 top
NOREF#225  -  []  9.33 77.92 0 top
NOREF#226  -  []  130.88 47.59 0 top
NOREF#227  -  []  58.14 40.73 0 top
NOREF#228  -  []  53.97 6.99 0 top
NOREF#229  -  []  138.9 28.68 90 top
NOREF#230  -  []  71.31 14.79 0 top
NOREF#231  -  []  11.21 26.29 0 top
NOREF#232  -  []  27.6 53.02 90 top
NOREF#233  -  []  2.03 65.88 0 top
NOREF#234  -  []  70.21 6.65 0 top
NOREF#235  -  []  40.72 78.5 90 top
NOREF#236  -  []  51.69 0.05 90 top
NOREF#237  -  []  18.25 28.92 90 top
NOREF#238  -  []  119.26 59.93 90 top
NOREF#239  -  []  20.74 -70.17 0 top
NOREF#240  -  []  44.15 56.22 0 top
NOREF#241  -  []  31.53 13.97 0 top
NOREF#242  -  []  46.98 38.92 0 top
NOREF#243  -  []  12.86 36.58 0 top
NOREF#244  -  []  40.57 1.45 0 top
NOREF#245  -  []  129 51.63 90 top
NOREF#246  -  []  12.76 36.9 0 top
NOREF#247  -  []  129.79 10.16 0 top
NOREF#248  -  []  85.89 33.02 0 top
NOREF#249  -  []  128.99 20.36 0 top
NOREF#250  -  []  46.59 41.59 90 top
NOREF#251  -  []  129 51.11 0 top
NOREF#252  -  []  103.57 20.14 0 top
NOREF#253  -  []  35.64 69.93 90 top
NOREF#254  -  []  66.79 18.93 0 top
NOREF#255  -  []  65 18.65 0 top
NOREF#256  -  []  31.44 65.78 90 top
NOREF#257  -  []  29.85 9.27 90 top
NOREF#258  -  []  41.33 20.9 0 top
NOREF#259  -  []  104.72 20.14 90 top
NOREF#260  -  []  98.73 48.33 90 top
NOREF#261  -  []  55.89 46.57 90 top
NOREF#262  -  []  31.75 67.18 0 top
NOREF#263  -  []  73.81 77.04 0 top
NOREF#264  -  []  110.71 19.04 90 top
NOREF#265  -  []  89.73 48.33 0 top
NOREF#266  -  []  22.04 45.66 90 top
NOREF#267  -  []  64.3 61.79 90 top
NOREF#268  -  []  35.85 35.12 0 top
NOREF#269  -  []  65.29 19.43 90 top
NOREF#270  -  []  139.45 28.88 90 top
NOREF#271  -  []  62.04 62.14 0 top
NOREF#272  -  []  82.06 5.95 90 top
NOREF#273  -  []  141.43 50.04 90 top
NOREF#274  -  []  130.59 19.01 90 top
NOREF#275  -  []  129 51.63 0 top
NOREF#276  -  []  55.89 46.57 90 top
NOREF#277  -  []  40.57 4.45 90 top
NOREF#278  -  []  69.9 12.49 0 top
NOREF#279  -  []  4.19 74.33 90 top
NOREF#280  -  []  43.95 6.42 0 top
NOREF#281  -  []  31.44 65.78 0 top
NOREF#282  -  []  50.47 38.92 0 top
NOREF#283  -  []  18.54 12.48 90 top
NOREF#284  -  []  79.4 8 0 top
NOREF#285  -  []  2.81 78.87 0 top
NOREF#286  -  []  104.93 8.36 0 top
NOREF#287  -  []  5.48 76.82 90 top
NOREF#288  -  []  35.73 78.5 90 top
NOREF#289  -  []  32.75 14.84 90 top
NOREF#290  -  []  7.04 35.76 0 top
NOREF#291  -  []  113.59 40.19 90 top
NOREF#292  -  []  20.28 30.77 0 top
NOREF#293  -  []  48.01 22.1 0 top
NOREF#294  -  []  113.59 41.34 0 top
NOREF#295  -  []  105.41 23.87 0 top
NOREF#296  -  []  105.97 2.16 0 top
NOREF#297  -  []  138.9 28.68 0 top
NOREF#298  -  []  101.64 70.07 0 top
NOREF#299  -  []  129.32 50.49 90 top
NOREF#300  -  []  70.14 54.91 90 top
NOREF#301  -  []  4.06 77.12 90 top
NOREF#302  -  []  145.09 96.43 0 top
NOREF#303  -  []  -356.61 -245.34 0 top
NOREF#304  -  []  42.22 4.45 0 top
NOREF#305  -  []  54.99 5.97 90 top
NOREF#306  -  []  139.54 6.51 90 top
NOREF#307  -  []  3.34 59.1 90 top
NOREF#308  -  []  50.8 39.02 90 top
NOREF#309  -  []  87.63 76.45 0 top
NOREF#310  -  []  120.79 13.94 0 top
NOREF#311  -  []  51.74 38.92 90 top
NOREF#312  -  []  21.92 30.97 0 top
NOREF#313  -  []  9.38 -2.63 0 top
NOREF#314  -  []  113.92 40.29 90 top
NOREF#315  -  []  55.54 50.16 90 top
NOREF#316  -  []  50.54 19.56 90 top
NOREF#317  -  []  27.49 12.34 0 top
NOREF#318  -  []  119.79 11.69 0 top
NOREF#319  -  []  86.94 31.55 0 top
NOREF#320  -  []  31.43 14.3 0 top
NOREF#321  -  []  8.2 35.11 90 top
NOREF#322  -  []  45.9 42.27 90 top
NOREF#323  -  []  10.75 5.27 90 top
NOREF#324  -  []  69.91 8.8 0 top
NOREF#325  -  []  108.14 22.92 0 top
NOREF#326  -  []  80.64 6.25 90 top
NOREF#327  -  []  23.56 32.7 90 top
NOREF#328  -  []  27.6 53.02 0 top
NOREF#329  -  []  19.78 68.48 90 top
NOREF#330  -  []  34.76 35.22 0 top
NOREF#331  -  []  79.76 56.36 90 top
NOREF#332  -  []  24.74 -2.63 0 top
NOREF#333  -  []  129.79 10.16 0 top
NOREF#334  -  []  54.74 6.88 0 top
NOREF#335  -  []  18.03 14.79 90 top
NOREF#336  -  []  44.97 6.42 0 top
NOREF#337  -  []  92.92 32.07 90 top
NOREF#338  -  []  11.73 7.08 0 top
NOREF#339  -  []  33.57 73.15 0 top
NOREF#340  -  []  141.03 47.24 90 top
NOREF#341  -  []  10.75 5.27 90 top
NOREF#342  -  []  0.43 64.65 0 top
NOREF#343  -  []  114.16 64.23 0 top
NOREF#344  -  []  5.48 5.95 90 top
NOREF#345  -  []  -318.55 273.65 0 top
NOREF#346  -  []  55.46 48.11 0 top
NOREF#347  -  []  129.32 54.93 90 top
NOREF#348  -  []  11.43 5.97 0 top
NOREF#349  -  []  57.57 48.11 90 top
NOREF#350  -  []  49.72 38.41 0 top
NOREF#351  -  []  42.72 6.42 0 top
NOREF#352  -  []  105.41 23.22 90 top
NOREF#353  -  []  129 57.84 0 top
NOREF#354  -  []  19.37 13.53 90 top
NOREF#355  -  []  129.79 10.16 0 top
NOREF#356  -  []  139.48 18.79 90 top
NOREF#357  -  []  75.29 10.09 90 top
NOREF#358  -  []  74.56 77.04 0 top
NOREF#359  -  []  46.59 46.54 0 top
NOREF#360  -  []  29.65 9.67 0 top
NOREF#361  -  []  17.99 43.26 90 top
NOREF#362  -  []  70 13.44 90 top
NOREF#363  -  []  70.45 12.59 0 top
NOREF#364  -  []  86.94 31.55 90 top
NOREF#365  -  []  19.09 43.36 90 top
NOREF#366  -  []  129.79 10.16 0 top
NOREF#367  -  []  75.04 9.44 90 top
NOREF#368  -  []  13.91 36.25 90 top
NOREF#369  -  []  38.81 32.17 90 top
NOREF#370  -  []  14.28 9.67 0 top
NOREF#371  -  []  129 56.08 90 top
NOREF#372  -  []  9.91 60.62 90 top
NOREF#373  -  []  32.94 73.33 0 top
NOREF#374  -  []  41.98 19.75 90 top
NOREF#375  -  []  83.14 46.91 0 top
NOREF#376  -  []  87.63 75.45 90 top
NOREF#377  -  []  129.32 49.34 90 top
NOREF#378  -  []  124.97 42.05 90 top
NOREF#379  -  []  108.42 2.56 0 top
NOREF#380  -  []  26.79 5.97 0 top
NOREF#381  -  []  35.01 70.1 90 top
NOREF#382  -  []  45.25 56.32 90 top
NOREF#383  -  [unnamed#2]  138.68 72.39 0 top
NOREF#384  -  []  70.26 15.11 0 top
NOREF#385  -  []  14.07 9.88 0 top
NOREF#386  -  []  31.44 5.27 0 top
NOREF#387  -  []  32.09 7.08 0 top
NOREF#388  -  []  54.51 19.78 0 top
NOREF#389  -  []  58.61 68.63 90 top
NOREF#390  -  []  15.28 71.98 0 top
NOREF#391  -  []  22.41 32.7 0 top
NOREF#392  -  []  194.3 38.93 0 bottom
NOREF#393  -  [unnamed#2]  114.94 3.18 180 bottom
NOREF#394  -  []  30.35 67.69 180 bottom
NOREF#395  -  [unnamed#2]  3.81 83.82 180 bottom
NOREF#396  -  []  134.11 3.3 180 bottom
NOREF#397  -  [unnamed#2]  138.68 72.39 180 bottom
NOREF#398  -  []  23.11 68.2 180 bottom
Q1  $  [SC70_3]  38.23 61.98 180 top
Q3  $  [SC70_3]  7.11 52.07 90 top
Q4  $  [SC70_3]  7.11 49.28 90 top
Q5  $  [SC70_3]  7.11 46.48 90 top
Q6  $  [SC70_3]  7.11 43.69 90 top
Q8  $  [SC70_3]  72.14 19.81 90 top
Q9  $  [SC70_3]  126.75 19.43 180 top
Q10  $  [SC70_3]  67.94 10.16 270 top
Q11  $  [SC70_3]  77.98 77.98 180 bottom
Q12  $  [SC70_3]  75.18 77.98 180 bottom
Q13  $  [SC70_3]  72.39 77.98 180 bottom
QZ1  $  [XTAL2-3P2X1P5-SM]  89.66 65.79 0 top
QZ2  $  [XTAL2-3P2X1P5-SM]  48.01 50.42 0 top
R1  $  [0402_CC]  85.98 84.07 0 top
R2  $  [0402_CC]  87.63 84.07 0 top
R3  $  [0402_CC]  78.11 81.41 270 top
R4  $  [0402_CC]  1.52 80.39 90 top
R5  $  [0402_CC]  87.88 78.99 180 top
R6  100K  [0402_CC]  54.23 78.36 90 top
R7  $  [0402_CC]  55.24 78.36 270 top
R8  $  [0402_CC]  56.26 78.36 270 top
R9  100K  [0402_CC]  57.28 78.36 90 top
R10  $  [0402_CC]  16.13 78.23 180 top
R11  $  [0402_CC]  87.88 77.98 0 top
R12  $  [0402_CC]  1.52 77.34 90 top
R13  $  [0402_CC]  78.11 77.34 90 top
R14  $  [0402_CC]  23.24 76.45 270 top
R15  $  [0402_CC]  25.27 76.45 270 top
R16  $  [0402_CC]  29.08 76.45 270 top
R17  $  [0402_CC]  2.79 74.8 270 top
R18  15K  [RC0402_25]  10.67 74.8 270 top
R19  $  [RC0402_25]  12.7 74.8 270 top
R20  $  [0402_CC]  17.78 74.8 270 top
R21  10K  [0402_CC]  39.75 73.66 180 top
R22  $  [0402_CC]  94.11 73.66 0 top
R23  $  [0402_CC]  96.14 73.66 0 top
R24  $  [0402_CC]  99.44 73.66 180 top
R25  $  [0402_CC]  101.47 73.66 180 top
R26  12K  [RC0402_25]  11.18 73.28 0 top
R27  $  [RC0402_25]  63.25 73.28 270 top
R28  $  [0402_CC]  64.26 73.28 90 top
R29  $  [RC0402_25]  65.28 73.28 270 top
R30  $  [RC0402_25]  66.55 73.28 270 top
R31  $  [0402_CC]  67.56 73.28 90 top
R32  $  [RC0402_25]  68.58 73.28 270 top
R33  $  [0402_CC]  73.28 73.28 90 top
R34  $  [0402_CC]  74.3 73.28 270 top
R35  $  [0402_CC]  75.31 73.28 90 top
R36  $  [0402_CC]  77.34 73.28 90 top
R37  $  [0402_CC]  78.36 73.28 270 top
R38  $  [0402_CC]  39.75 72.64 0 top
R39  $  [0402_CC]  95.88 72.14 180 top
R40  2.2K  [0402_CC]  121.67 72.01 0 top
R41  $  [0402_CC]  123.7 72.01 0 top
R42  $  [0402_CC]  103.5 71.88 180 top
R43  $  [0603_CC]  31.62 71.63 90 top
R44  $  [0603_CC]  36.96 71.63 270 top
R45  $  [0402_CC]  39.75 71.63 0 top
R46  $  [0402_CC]  11.68 71.5 270 top
R47  $  [0402_CC]  12.7 71.5 90 top
R48  2.2K  [0402_CC]  121.67 70.99 0 top
R49  $  [0402_CC]  123.7 70.99 0 top
R50  $  [0402_CC]  125.73 70.99 180 top
R51  $  [0402_CC]  39.75 70.61 0 top
R52  $  [0402_CC]  128.91 70.1 180 top
R53  $  [0402_CC]  86.49 69.98 90 top
R54  $  [0402_CC]  87.76 69.98 90 top
R55  $  [0201_CC]  88.65 69.98 270 top
R56  $  [0402_CC]  89.53 69.98 270 top
R57  100K  [0402_CC]  91.57 69.98 270 top
R58  $  [0201_CC]  92.46 69.98 90 top
R59  $  [0201_CC]  93.6 69.98 90 top
R60  $  [0402_CC]  39.75 69.6 0 top
R61  $  [0402_CC]  114.55 69.09 0 top
R62  $  [0402_CC]  128.91 69.09 180 top
R63  $  [RC0402_25]  138.68 69.09 0 top
R64  $  [0402_CC]  39.75 68.58 0 top
R65  $  [RC0402_25]  82.3 68.07 0 top
R66  $  [0402_CC]  128.91 67.82 180 top
R67  $  [RC0402_25]  138.68 67.82 0 top
R68  $  [RC0402_25]  113.16 67.18 90 top
R69  $  [RC0402_25]  114.17 67.18 90 top
R70  $  [RC0402_25]  115.19 67.18 90 top
R71  $  [RC0402_25]  116.2 67.18 90 top
R72  $  [RC0402_25]  117.22 67.18 90 top
R73  $  [RC0402_25]  118.24 67.18 90 top
R74  $  [RC0402_25]  119.25 67.18 90 top
R75  $  [RC0402_25]  121.54 67.18 0 top
R76  $  [0402_CC]  28.7 67.06 0 top
R77  $  [RC0402_25]  38.99 67.06 270 top
R78  $  [0402_CC]  40 67.06 90 top
R79  $  [0402_CC]  13.46 66.8 90 top
R80  $  [0402_CC]  14.48 66.8 90 top
R81  10K  [0402_CC]  15.49 66.8 90 top
R82  $  [0402_CC]  16.51 66.8 90 top
R83  $  [0402_CC]  17.53 66.8 90 top
R84  10K  [0402_CC]  18.54 66.8 90 top
R85  $  [0402_CC]  19.56 66.8 90 top
R86  $  [0402_CC]  41.4 66.68 180 top
R87  $  [0402_CC]  99.57 66.55 270 top
R88  $  [0402_CC]  100.58 66.55 270 top
R89  $  [0402_CC]  128.91 66.55 180 top
R90  $  [RC0402_25]  138.68 66.55 0 top
R91  10K  [0402_CC]  85.22 66.42 270 top
R92  $  [0402_CC]  86.49 66.42 270 top
R93  $  [0402_CC]  101.85 66.04 270 top
R94  $  [0402_CC]  102.87 66.04 270 top
R95  $  [RC0402_25]  121.54 66.04 0 top
R96  $  [0402_CC]  128.91 65.28 180 top
R97  $  [RC0402_25]  138.68 65.28 0 top
R98  $  [RC0402_25]  82.3 65.02 0 top
R99  $  [RC0402_25]  121.54 65.02 0 top
R101  $  [RC0402_25]  121.54 64.01 0 top
R102  $  [0402_CC]  77.72 47.31 0 bottom
R103  $  [0402_CC]  29.59 63.5 0 top
R104  4.7M  [RC0402_25]  89.66 63.37 180 top
R105  510K  [0402_CC]  94.74 63.37 180 top
R106  $  [0402_CC]  64.01 63.25 270 top
R107  $  [0402_CC]  65.28 63.25 270 top
R108  $  [0402_CC]  66.55 63.25 270 top
R109  $  [0402_CC]  67.82 63.25 270 top
R110  $  [RC0402_25]  121.54 62.99 0 top
R111  $  [RC0402_25]  124.08 62.99 0 top
R112  $  [0402_CC]  29.59 62.48 0 top
R113  $  [0201_CC]  84.45 62.48 180 top
R114  $  [0201_CC]  86.61 62.48 180 top
R115  $  [0402_CC]  44.07 62.23 90 top
R116  $  [RC0402_25]  121.54 61.98 0 top
R117  $  [0402_CC]  124.08 61.98 180 top
R118  $  [0402_CC]  111.38 61.6 0 top
R119  $  [RC0402_25]  121.54 60.96 0 top
R120  10K  [0402_CC]  42.16 60.58 180 top
R121  $  [0402_CC]  109.35 60.2 0 top
R122  0  [0402_CC]  111.38 60.2 180 top
R123  $  [RC0402_25]  121.54 59.94 0 top
R124  $  [0402_CC]  26.92 59.82 90 top
R125  $  [0402_CC]  28.96 59.82 270 top
R126  $  [0402_CC]  29.97 59.82 270 top
R127  $  [0402_CC]  51.05 59.82 180 top
R128  $  [0402_CC]  42.16 59.56 180 top
R129  $  [0402_CC]  109.35 58.93 0 top
R130  0  [0402_CC]  111.38 58.93 180 top
R131  $  [RC0402_25]  121.54 58.93 0 top
R132  $  [0402_CC]  51.05 58.8 180 top
R133  0  [0402_CC]  127.25 58.04 0 top
R134  $  [0402_CC]  51.05 57.79 180 top
R135  $  [0402_CC]  111.12 57.66 90 top
R136  $  [0402_CC]  112.14 57.66 90 top
R137  $  [RC0402_25]  113.16 57.66 270 top
R138  $  [RC0402_25]  114.17 57.66 270 top
R139  $  [RC0402_25]  115.19 57.66 270 top
R140  $  [RC0402_25]  116.2 57.66 270 top
R141  $  [RC0402_25]  117.22 57.66 270 top
R142  $  [RC0402_25]  118.24 57.66 270 top
R143  $  [RC0402_25]  119.25 57.66 270 top
R144  $  [RC0402_25]  120.27 57.66 270 top
R145  10K  [0402_CC]  24.51 57.28 180 top
R146  0  [0402_CC]  18.67 57.02 90 top
R147  0  [0402_CC]  127.25 57.02 0 top
R148  $  [0402_CC]  51.05 56.77 180 top
R149  $  [0402_CC]  33.4 56.52 180 top
R150  $  [0402_CC]  24.51 56.26 180 top
R151  10K  [0402_CC]  127.25 56.13 180 top
R152  $  [0402_CC]  33.4 55.5 180 top
R153  0  [0402_CC]  127.25 55.12 0 top
R154  $  [0402_CC]  14.99 54.99 270 top
R155  $  [0402_CC]  16 54.99 270 top
R156  $  [0402_CC]  17.4 54.99 270 top
R157  $  [0402_CC]  18.67 54.99 270 top
R159  $  [0201_CC]  43.94 54.86 270 top
R160  $  [0201_CC]  44.7 54.86 270 top
R161  $  [0402_CC]  33.4 54.48 180 top
R162  $  [RC0402_25]  45.59 54.36 270 top
R163  100K  [0402_CC]  108.97 53.98 180 top
R164  $  [0201_CC]  24.64 53.85 180 top
R165  $  [0402_CC]  33.4 53.47 180 top
R166  $  [0402_CC]  46.61 53.47 90 top
R167  $  [0402_CC]  47.62 53.47 90 top
R168  $  [0402_CC]  48.89 53.47 270 top
R169  $  [0402_CC]  49.91 53.47 270 top
R170  $  [0201_CC]  24.64 53.09 180 top
R171  0  [0402_CC]  127.25 52.83 0 top
R172  $  [0402_CC]  4.7 52.07 0 top
R173  10K  [0402_CC]  127.25 51.82 180 top
R174  $  [RC0805_OV]  60.71 51.69 90 top
R175  $  [RC0603_OV]  58.93 51.44 270 top
R176  $  [RC0402_25]  27.94 51.05 270 top
R177  0  [0402_CC]  127.25 50.8 0 top
R178  $  [RC0402_25]  4.7 50.67 0 top
R179  $  [RC0805_OV]  38.86 50.55 90 top
R180  $  [0402_CC]  17.91 50.17 90 top
R181  $  [0402_CC]  20.45 50.17 270 top
R182  $  [0402_CC]  21.46 50.17 270 top
R183  $  [0402_CC]  28.96 50.17 90 top
R184  $  [0402_CC]  29.97 50.17 90 top
R185  $  [RC0805_OV]  41.33 49.61 0 top
R186  0  [0402_CC]  127.25 49.66 0 top
R187  $  [0402_CC]  4.7 49.28 0 top
R188  $  [0402_CC]  44.2 48.39 270 top
R189  $  [0402_CC]  45.21 48.39 270 top
R190  $  [0402_CC]  46.23 48.39 270 top
R191  $  [0402_CC]  49.78 48.39 270 top
R192  $  [RC0603_OV]  34.16 48.13 180 top
R193  1M  [0201_CC]  48.01 48.01 180 top
R194  $  [RC0402_25]  4.7 47.88 0 top
R195  10K  [0402_CC]  16 47.37 180 top
R196  $  [0402_CC]  128.65 47.24 0 top
R197  $  [0402_CC]  24.89 46.86 180 top
R198  $  [0402_CC]  4.7 46.48 0 top
R199  $  [0402_CC]  16 46.36 180 top
R200  $  [0402_CC]  24.89 45.85 180 top
R201  $  [0402_CC]  75.06 47.69 90 bottom
R202  $  [0402_CC]  130.94 45.72 180 top
R203  $  [0402_CC]  132.97 45.72 0 top
R204  $  [0402_CC]  89.53 53.85 90 bottom
R205  150  [0402_CC]  77.67 50.11 270 bottom
R206  $  [0402_CC]  13.21 45.21 180 top
R207  10K  [0402_CC]  77.98 53.59 0 bottom
R208  10K  [0402_CC]  79.25 52.2 180 bottom
R209  $  [0201_CC]  83.82 51.63 0 bottom
R210  $  [0402_CC]  79.38 55.31 270 bottom
R211  $  [0201_CC]  83.82 50.99 180 bottom
R212  $  [RC0402_25]  4.7 45.09 0 top
R213  $  [0402_CC]  24.89 44.83 180 top
R214  $  [0402_CC]  59.69 44.58 270 top
R215  $  [0402_CC]  60.71 44.58 270 top
R216  $  [0402_CC]  130.94 44.45 0 top
R217  0  [0402_CC]  132.97 44.45 0 top
R218  $  [0402_CC]  139.32 43.94 270 top
R219  $  [0402_CC]  12.83 43.82 90 top
R220  $  [0402_CC]  24.89 43.82 180 top
R221  $  [0402_CC]  4.7 43.69 0 top
R222  $  [RC0805_OV]  36.83 43.43 180 top
R223  10K  [0402_CC]  103.5 43.28 270 top
R224  $  [0402_CC]  89.92 42.8 270 top
R225  $  [RC0402_25]  4.7 42.29 0 top
R226  $  [0402_CC]  10.03 41.91 270 top
R227  $  [0201_CC]  17.78 41.91 270 top
R228  $  [0201_CC]  18.54 41.91 270 top
R229  10K  [0402_CC]  88.77 41.66 270 top
R230  $  [RC0402_25]  19.43 41.4 270 top
R231  $  [0402_CC]  20.45 40.51 90 top
R232  $  [0402_CC]  21.46 40.51 90 top
R233  $  [0402_CC]  120.02 40.13 90 top
R234  $  [RC0805_OV]  36.83 39.88 180 top
R235  $  [0402_CC]  54.74 39.75 270 top
R236  $  [0402_CC]  44.2 39.5 90 top
R237  $  [0402_CC]  45.21 39.5 90 top
R238  0  [0402_CC]  138.3 39.37 90 top
R239  10K  [0402_CC]  103.5 38.74 90 top
R240  $  [RC0603_OV]  60.83 38.48 90 top
R241  $  [RC0805_OV]  62.74 38.48 270 top
R242  0  [0402_CC]  54.74 38.23 270 top
R243  $  [RC0603_OV]  46.86 37.47 180 top
R244  $  [RC0805_OV]  36.83 36.32 180 top
R245  $  [RC0402_25]  84.84 35.81 90 top
R246  4.7K  [RC0402_25]  86.87 35.81 270 top
R247  $  [RC0402_25]  87.88 35.81 90 top
R248  0  [0402_CC]  77.98 35.31 0 top
R249  $  [0402_CC]  89.15 35.18 180 top
R250  $  [RC0603_OV]  50.67 35.05 270 top
R251  $  [RC0805_OV]  52.45 35.05 270 top
R252  $  [0402_CC]  20.32 34.29 0 top
R253  $  [RC0402_25]  84.84 33.15 270 top
R254  4.7K  [RC0402_25]  85.85 33.15 90 top
R255  $  [0402_CC]  20.32 33.02 0 top
R256  $  [0402_CC]  72.9 32.26 0 top
R257  $  [0402_CC]  75.06 32.26 0 top
R258  $  [0402_CC]  78.87 32.26 0 top
R259  $  [0402_CC]  80.52 32.26 0 top
R260  $  [RC0805_OV]  28.32 31.12 90 top
R261  $  [RC0805_OV]  65.91 30.35 0 top
R263  $  [0402_CC]  95.5 29.08 180 top
R264  $  [0402_CC]  86.87 28.96 90 top
R265  $  [0402_CC]  111.38 28.83 270 top
R266  $  [0402_CC]  115.82 28.83 270 top
R267  $  [0402_CC]  95.5 28.07 180 top
R268  $  [0402_CC]  135 27.81 90 top
R269  $  [RC0402_25]  137.03 27.81 270 top
R271  $  [0402_CC]  86.87 27.31 270 top
R272  $  [0402_CC]  139.57 27.31 180 top
R273  100K  [0402_CC]  141.22 27.31 180 top
R274  $  [0402_CC]  95.5 27.05 180 top
R276  $  [0402_CC]  139.57 26.29 0 top
R277  $  [0402_CC]  141.22 26.29 180 top
R278  $  [0402_CC]  103 25.4 0 top
R279  1K  [0402_CC]  139.57 25.27 0 top
R280  $  [0402_CC]  27.69 25.02 0 top
R281  $  [RC0402_25]  4.7 24.77 180 top
R282  $  [0402_CC]  15.24 24.77 180 top
R283  $  [0402_CC]  43.81 24.64 270 top
R284  $  [0402_CC]  11.81 24.38 270 top
R285  $  [0402_CC]  103 24.38 0 top
R286  1K  [0402_CC]  139.57 24.26 0 top
R287  $  [0402_CC]  113.66 24 180 top
R288  $  [0402_CC]  27.69 24 0 top
R289  $  [0402_CC]  34.42 24 180 top
R290  $  [0402_CC]  121.28 23.62 270 top
R291  $  [0402_CC]  122.3 23.62 270 top
R292  10K  [0402_CC]  123.32 23.62 270 top
R293  10K  [0402_CC]  124.33 23.62 270 top
R294  $  [0603_CC]  25.02 23.5 90 top
R295  $  [0402_CC]  2.54 23.37 180 top
R296  $  [0402_CC]  4.7 23.37 0 top
R297  $  [0402_CC]  113.66 22.99 180 top
R298  $  [0402_CC]  27.69 22.99 180 top
R299  $  [0402_CC]  34.42 22.99 0 top
R300  $  [RC0402_25]  75.44 22.35 90 top
R301  0  [0402_CC]  79.25 22.35 270 top
R302  $  [0402_CC]  80.52 22.35 270 top
R303  $  [0402_CC]  82.42 22.35 90 top
R304  510  [0402_CC]  83.44 22.35 90 top
R305  $  [0402_CC]  84.45 22.35 90 top
R306  $  [0402_CC]  101.47 22.35 270 top
R307  10K  [0402_CC]  102.49 22.35 90 top
R308  $  [0402_CC]  103.5 22.35 90 top
R309  $  [RC0402_25]  43.31 21.84 0 top
R310  $  [0402_CC]  135 21.46 0 top
R311  $  [0402_CC]  68.83 21.08 90 top
R312  $  [0402_CC]  95.38 49.15 180 bottom
R313  1M  [0402_CC]  69.85 21.08 270 top
R314  $  [0402_CC]  119.13 20.83 270 top
R315  $  [0402_CC]  120.27 20.83 270 top
R316  $  [0402_CC]  135 20.45 180 top
R317  $  [RC0402_25]  42.8 20.32 270 top
R318  $  [0402_CC]  140.59 20.07 90 top
R319  100K  [0402_CC]  68.83 19.43 90 top
R320  $  [0402_CC]  69.85 19.43 90 top
R321  $  [0402_CC]  75.44 19.43 90 top
R322  $  [0402_CC]  135 19.43 180 top
R323  $  [0402_CC]  42.16 18.8 0 top
R324  $  [0402_CC]  120.27 18.8 90 top
R325  $  [0402_CC]  121.28 18.8 90 top
R326  $  [0402_CC]  122.3 18.8 90 top
R327  $  [0402_CC]  123.32 18.8 90 top
R328  $  [0402_CC]  124.33 18.8 90 top
R329  $  [0402_CC]  30.99 18.67 90 top
R330  $  [0402_CC]  32 18.67 270 top
R331  $  [0402_CC]  33.02 18.67 270 top
R332  $  [0402_CC]  2.54 17.53 0 top
R333  $  [0402_CC]  4.57 17.53 180 top
R334  $  [0603_CC]  103.38 17.4 0 top
R335  $  [0603_CC]  106.17 17.4 180 top
R336  $  [0603_CC]  110.74 17.4 0 top
R337  $  [0603_CC]  113.54 17.4 180 top
R338  10K  [0402_CC]  69.85 17.15 90 top
R339  $  [0402_CC]  71.88 17.15 90 top
R340  100K  [0402_CC]  22.35 16.76 180 top
R341  $  [0402_CC]  42.16 16.76 0 top
R342  $  [0402_CC]  2.54 16.51 180 top
R343  $  [0402_CC]  4.57 16.51 0 top
R344  $  [RC0402_25]  120.27 16.51 90 top
R345  0  [0402_CC]  121.28 16.51 90 top
R346  $  [0402_CC]  122.3 16.51 90 top
R347  $  [0402_CC]  123.32 16.51 90 top
R348  $  [0402_CC]  124.33 16.51 90 top
R349  $  [0402_CC]  126.75 16.51 90 top
R350  $  [RC0402_25]  127.76 16.51 90 top
R351  $  [0402_CC]  128.78 16.51 90 top
R352  $  [0402_CC]  129.79 16.51 90 top
R353  $  [0402_CC]  130.81 16.51 90 top
R354  $  [0402_CC]  134.11 16.51 270 top
R355  $  [0402_CC]  136.4 16.51 270 top
R356  $  [0402_CC]  137.41 16.51 270 top
R357  $  [0402_CC]  138.43 16.51 270 top
